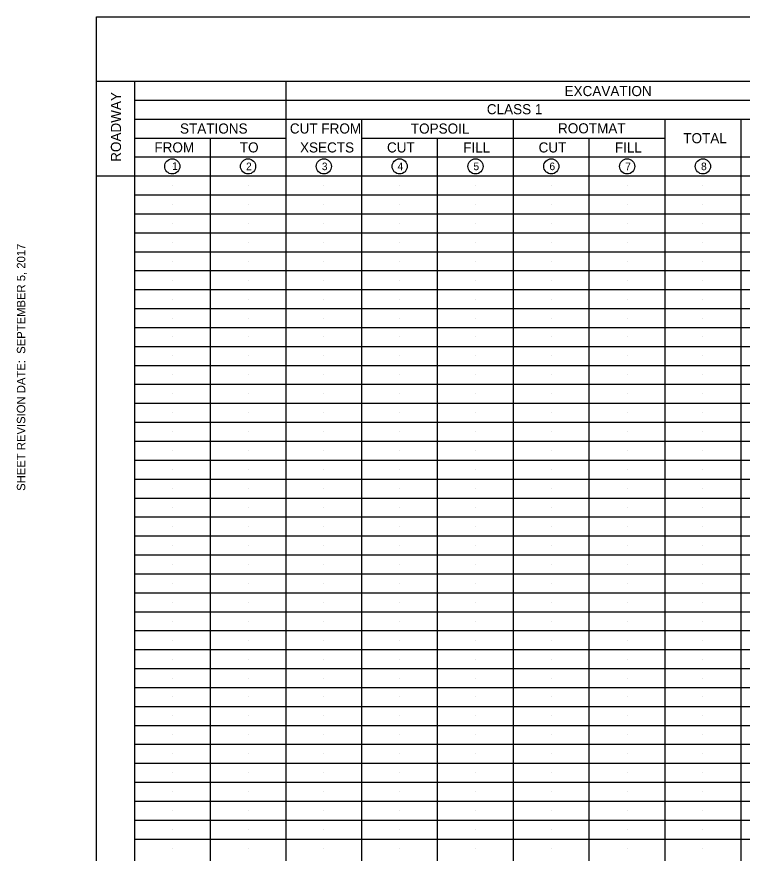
# Model space of a CAD drawing. Extents: x 1.3 to 38.6, y 0 to 21.1.
# Drawn here: x 1.3 to 9.92, y 11.12 to 21.06 of the extents above; entities that cross this region are included whole.
import ezdxf

# ---------------------------------------------------------------- set-up
doc = ezdxf.new("R2010")
doc.units = 0
for name, color, linetype in [('G-ANNO-TABL', 7, 'Continuous'), ('G-ANNO-TITL', 7, 'Continuous'), ('G-USER-LINE', 7, 'Continuous'), ('G-USER-TEXT', 7, 'Continuous')]:
    doc.layers.add(name, color=color, linetype=linetype)

msp = doc.modelspace()

# ---------------------------------------------------------------- linework, layer by layer
at = {"layer": 'G-ANNO-TABL'}
for p, q in [((2.248, 1.1651), (2.248, 21.0551)), ((2.248, 21.055), (22.498, 21.055)), ((2.248, 20.29), (2.249, 20.29)), ((2.248, 20.29), (22.498, 20.29)), ((2.698, 20.29), (2.698, 1.165)), ((4.498, 20.2901), (4.498, 1.1651)), ((2.698, 20.065), (17.098, 20.065)), ((2.698, 19.84), (22.498, 19.84)), ((5.398, 4.54), (5.398, 19.8401)), ((7.198, 4.54), (7.198, 19.8401)), ((8.998, 4.54), (8.998, 19.8401)), ((9.898, 19.8401), (9.898, 4.54)), ((2.698, 19.615), (4.498, 19.615)), ((3.598, 19.6151), (3.598, 17.815)), ((5.398, 19.615), (8.998, 19.615)), ((6.298, 4.54), (6.298, 19.6151)), ((8.098, 4.54), (8.098, 19.6151)), ((2.698, 19.39), (22.498, 19.39)), ((2.248, 19.165), (22.498, 19.165)), ((2.698, 18.94), (22.498, 18.94)), ((2.698, 18.715), (22.498, 18.715)), ((2.698, 18.49), (22.498, 18.49)), ((2.698, 18.265), (22.498, 18.265)), ((2.698, 18.04), (22.498, 18.04)), ((2.698, 17.815), (22.498, 17.815)), ((3.598, 17.815), (3.598, 17.59)), ((2.698, 17.59), (22.498, 17.59)), ((3.598, 17.59), (3.598, 16.915)), ((2.698, 17.365), (22.498, 17.365)), ((2.698, 17.14), (22.498, 17.14)), ((2.698, 16.915), (22.498, 16.915)), ((3.598, 16.915), (3.598, 14.665)), ((2.698, 16.69), (22.498, 16.69)), ((2.698, 16.465), (22.498, 16.465)), ((2.698, 16.24), (22.498, 16.24)), ((2.698, 16.015), (22.498, 16.015)), ((2.698, 15.79), (22.498, 15.79)), ((2.698, 15.565), (22.498, 15.565)), ((2.698, 15.34), (22.498, 15.34)), ((2.698, 15.115), (22.498, 15.115)), ((2.698, 14.89), (22.498, 14.89)), ((2.698, 14.665), (22.498, 14.665)), ((3.598, 14.665), (3.598, 1.165)), ((2.698, 14.44), (22.498, 14.44)), ((2.698, 14.215), (22.498, 14.215)), ((2.698, 13.99), (22.498, 13.99)), ((2.698, 13.765), (22.498, 13.765)), ((2.698, 13.54), (22.498, 13.54)), ((2.698, 13.315), (22.498, 13.315)), ((2.698, 13.09), (22.498, 13.09)), ((2.698, 12.865), (22.498, 12.865)), ((2.698, 12.64), (22.498, 12.64)), ((2.698, 12.415), (22.498, 12.415)), ((2.698, 12.19), (22.498, 12.19)), ((2.698, 11.965), (22.498, 11.965)), ((2.698, 11.74), (22.498, 11.74)), ((2.698, 11.515), (22.498, 11.515)), ((2.698, 11.29), (22.498, 11.29))]:
    msp.add_line(p, q, dxfattribs=at)
at = {"layer": 'G-ANNO-TITL'}
for centre in [(3.1479, 19.278), (4.0479, 19.278), (4.9479, 19.278), (5.8479, 19.278), (6.7479, 19.278), (7.6479, 19.278), (8.5479, 19.278), (9.4479, 19.278)]:
    msp.add_circle(centre, 0.09, dxfattribs=at)
at = {"layer": 'G-USER-LINE'}
for p, q in [((3.148, 19.5025), (3.148, 19.5025)), ((4.048, 19.5025), (4.048, 19.5025)), ((5.848, 19.5025), (5.848, 19.5025)), ((6.748, 19.5025), (6.748, 19.5025)), ((7.648, 19.5025), (7.648, 19.5025)), ((8.548, 19.5025), (8.548, 19.5025)), ((3.148, 19.2775), (3.148, 19.2775)), ((4.048, 19.2775), (4.048, 19.2775)), ((4.948, 19.2775), (4.948, 19.2775)), ((5.848, 19.2775), (5.848, 19.2775)), ((6.748, 19.2775), (6.748, 19.2775)), ((7.648, 19.2775), (7.648, 19.2775)), ((8.548, 19.2775), (8.548, 19.2775)), ((9.448, 19.2775), (9.448, 19.2775)), ((3.148, 19.0525), (3.148, 19.0525)), ((4.048, 19.0525), (4.048, 19.0525)), ((4.948, 19.0525), (4.948, 19.0525)), ((5.848, 19.0525), (5.848, 19.0525)), ((6.748, 19.0525), (6.748, 19.0525)), ((7.648, 19.0525), (7.648, 19.0525)), ((8.548, 19.0525), (8.548, 19.0525)), ((9.448, 19.0525), (9.448, 19.0525)), ((3.148, 18.8275), (3.148, 18.8275)), ((4.048, 18.8275), (4.048, 18.8275)), ((4.948, 18.8275), (4.948, 18.8275)), ((5.848, 18.8275), (5.848, 18.8275)), ((6.748, 18.8275), (6.748, 18.8275)), ((7.648, 18.8275), (7.648, 18.8275)), ((8.548, 18.8275), (8.548, 18.8275)), ((9.448, 18.8275), (9.448, 18.8275)), ((3.148, 18.6025), (3.148, 18.6025)), ((4.048, 18.6025), (4.048, 18.6025)), ((4.948, 18.6025), (4.948, 18.6025)), ((5.848, 18.6025), (5.848, 18.6025)), ((6.748, 18.6025), (6.748, 18.6025)), ((7.648, 18.6025), (7.648, 18.6025)), ((8.548, 18.6025), (8.548, 18.6025)), ((9.448, 18.6025), (9.448, 18.6025)), ((3.148, 18.3775), (3.148, 18.3775)), ((4.048, 18.3775), (4.048, 18.3775)), ((4.948, 18.3775), (4.948, 18.3775)), ((5.848, 18.3775), (5.848, 18.3775)), ((6.748, 18.3775), (6.748, 18.3775)), ((7.648, 18.3775), (7.648, 18.3775)), ((8.548, 18.3775), (8.548, 18.3775)), ((9.448, 18.3775), (9.448, 18.3775)), ((3.148, 18.1525), (3.148, 18.1525)), ((4.048, 18.1525), (4.048, 18.1525)), ((4.948, 18.1525), (4.948, 18.1525)), ((5.848, 18.1525), (5.848, 18.1525)), ((6.748, 18.1525), (6.748, 18.1525)), ((7.648, 18.1525), (7.648, 18.1525)), ((8.548, 18.1525), (8.548, 18.1525)), ((9.448, 18.1525), (9.448, 18.1525)), ((3.148, 17.9275), (3.148, 17.9275)), ((4.048, 17.9275), (4.048, 17.9275)), ((4.948, 17.9275), (4.948, 17.9275)), ((5.848, 17.9275), (5.848, 17.9275)), ((6.748, 17.9275), (6.748, 17.9275)), ((7.648, 17.9275), (7.648, 17.9275)), ((8.548, 17.9275), (8.548, 17.9275)), ((9.448, 17.9275), (9.448, 17.9275)), ((3.148, 17.7025), (3.148, 17.7025)), ((4.048, 17.7025), (4.048, 17.7025)), ((4.948, 17.7025), (4.948, 17.7025)), ((5.848, 17.7025), (5.848, 17.7025)), ((6.748, 17.7025), (6.748, 17.7025)), ((7.648, 17.7025), (7.648, 17.7025)), ((8.548, 17.7025), (8.548, 17.7025)), ((9.448, 17.7025), (9.448, 17.7025)), ((3.148, 17.4775), (3.148, 17.4775)), ((4.048, 17.4775), (4.048, 17.4775)), ((4.948, 17.4775), (4.948, 17.4775)), ((5.848, 17.4775), (5.848, 17.4775)), ((6.748, 17.4775), (6.748, 17.4775)), ((7.648, 17.4775), (7.648, 17.4775)), ((8.548, 17.4775), (8.548, 17.4775)), ((9.448, 17.4775), (9.448, 17.4775)), ((3.148, 17.2525), (3.148, 17.2525)), ((4.048, 17.2525), (4.048, 17.2525)), ((4.948, 17.2525), (4.948, 17.2525)), ((5.848, 17.2525), (5.848, 17.2525)), ((6.748, 17.2525), (6.748, 17.2525)), ((7.648, 17.2525), (7.648, 17.2525)), ((8.548, 17.2525), (8.548, 17.2525)), ((9.448, 17.2525), (9.448, 17.2525)), ((3.148, 17.0275), (3.148, 17.0275)), ((4.048, 17.0275), (4.048, 17.0275)), ((4.948, 17.0275), (4.948, 17.0275)), ((5.848, 17.0275), (5.848, 17.0275)), ((6.748, 17.0275), (6.748, 17.0275)), ((7.648, 17.0275), (7.648, 17.0275)), ((8.548, 17.0275), (8.548, 17.0275)), ((9.448, 17.0275), (9.448, 17.0275)), ((3.148, 16.8025), (3.148, 16.8025)), ((4.048, 16.8025), (4.048, 16.8025)), ((4.948, 16.8025), (4.948, 16.8025)), ((5.848, 16.8025), (5.848, 16.8025)), ((6.748, 16.8025), (6.748, 16.8025)), ((7.648, 16.8025), (7.648, 16.8025)), ((8.548, 16.8025), (8.548, 16.8025)), ((9.448, 16.8025), (9.448, 16.8025)), ((3.148, 16.5775), (3.148, 16.5775)), ((4.048, 16.5775), (4.048, 16.5775)), ((4.948, 16.5775), (4.948, 16.5775)), ((5.848, 16.5775), (5.848, 16.5775)), ((6.748, 16.5775), (6.748, 16.5775)), ((7.648, 16.5775), (7.648, 16.5775)), ((8.548, 16.5775), (8.548, 16.5775)), ((9.448, 16.5775), (9.448, 16.5775)), ((3.148, 16.3525), (3.148, 16.3525)), ((4.048, 16.3525), (4.048, 16.3525)), ((4.948, 16.3525), (4.948, 16.3525)), ((5.848, 16.3525), (5.848, 16.3525)), ((6.748, 16.3525), (6.748, 16.3525)), ((7.648, 16.3525), (7.648, 16.3525)), ((8.548, 16.3525), (8.548, 16.3525)), ((9.448, 16.3525), (9.448, 16.3525)), ((3.148, 16.1275), (3.148, 16.1275)), ((4.048, 16.1275), (4.048, 16.1275)), ((4.948, 16.1275), (4.948, 16.1275)), ((5.848, 16.1275), (5.848, 16.1275)), ((6.748, 16.1275), (6.748, 16.1275)), ((7.648, 16.1275), (7.648, 16.1275)), ((8.548, 16.1275), (8.548, 16.1275)), ((9.448, 16.1275), (9.448, 16.1275)), ((3.148, 15.9025), (3.148, 15.9025)), ((4.048, 15.9025), (4.048, 15.9025)), ((4.948, 15.9025), (4.948, 15.9025)), ((5.848, 15.9025), (5.848, 15.9025)), ((6.748, 15.9025), (6.748, 15.9025)), ((7.648, 15.9025), (7.648, 15.9025)), ((8.548, 15.9025), (8.548, 15.9025)), ((9.448, 15.9025), (9.448, 15.9025)), ((3.148, 15.6775), (3.148, 15.6775)), ((4.048, 15.6775), (4.048, 15.6775)), ((4.948, 15.6775), (4.948, 15.6775)), ((5.848, 15.6775), (5.848, 15.6775)), ((6.748, 15.6775), (6.748, 15.6775)), ((7.648, 15.6775), (7.648, 15.6775)), ((8.548, 15.6775), (8.548, 15.6775)), ((9.448, 15.6775), (9.448, 15.6775)), ((3.148, 15.4525), (3.148, 15.4525)), ((4.048, 15.4525), (4.048, 15.4525)), ((4.948, 15.4525), (4.948, 15.4525)), ((5.848, 15.4525), (5.848, 15.4525)), ((6.748, 15.4525), (6.748, 15.4525)), ((7.648, 15.4525), (7.648, 15.4525)), ((8.548, 15.4525), (8.548, 15.4525)), ((9.448, 15.4525), (9.448, 15.4525)), ((3.148, 15.2275), (3.148, 15.2275)), ((4.048, 15.2275), (4.048, 15.2275)), ((4.948, 15.2275), (4.948, 15.2275)), ((5.848, 15.2275), (5.848, 15.2275)), ((6.748, 15.2275), (6.748, 15.2275)), ((7.648, 15.2275), (7.648, 15.2275)), ((8.548, 15.2275), (8.548, 15.2275)), ((9.448, 15.2275), (9.448, 15.2275)), ((3.148, 15.0025), (3.148, 15.0025)), ((4.048, 15.0025), (4.048, 15.0025)), ((4.948, 15.0025), (4.948, 15.0025)), ((5.848, 15.0025), (5.848, 15.0025)), ((6.748, 15.0025), (6.748, 15.0025)), ((7.648, 15.0025), (7.648, 15.0025)), ((8.548, 15.0025), (8.548, 15.0025)), ((9.448, 15.0025), (9.448, 15.0025)), ((3.148, 14.7775), (3.148, 14.7775)), ((4.048, 14.7775), (4.048, 14.7775)), ((4.948, 14.7775), (4.948, 14.7775)), ((5.848, 14.7775), (5.848, 14.7775)), ((6.748, 14.7775), (6.748, 14.7775)), ((7.648, 14.7775), (7.648, 14.7775)), ((8.548, 14.7775), (8.548, 14.7775)), ((9.448, 14.7775), (9.448, 14.7775)), ((3.148, 14.5525), (3.148, 14.5525)), ((4.048, 14.5525), (4.048, 14.5525)), ((4.948, 14.5525), (4.948, 14.5525)), ((5.848, 14.5525), (5.848, 14.5525)), ((6.748, 14.5525), (6.748, 14.5525)), ((7.648, 14.5525), (7.648, 14.5525)), ((8.548, 14.5525), (8.548, 14.5525)), ((9.448, 14.5525), (9.448, 14.5525)), ((3.148, 14.3275), (3.148, 14.3275)), ((4.048, 14.3275), (4.048, 14.3275)), ((4.948, 14.3275), (4.948, 14.3275)), ((5.848, 14.3275), (5.848, 14.3275)), ((6.748, 14.3275), (6.748, 14.3275)), ((7.648, 14.3275), (7.648, 14.3275)), ((8.548, 14.3275), (8.548, 14.3275)), ((9.448, 14.3275), (9.448, 14.3275)), ((3.148, 14.1025), (3.148, 14.1025)), ((4.048, 14.1025), (4.048, 14.1025)), ((4.948, 14.1025), (4.948, 14.1025)), ((5.848, 14.1025), (5.848, 14.1025)), ((6.748, 14.1025), (6.748, 14.1025)), ((7.648, 14.1025), (7.648, 14.1025)), ((8.548, 14.1025), (8.548, 14.1025)), ((9.448, 14.1025), (9.448, 14.1025)), ((3.148, 13.8775), (3.148, 13.8775)), ((4.048, 13.8775), (4.048, 13.8775)), ((4.948, 13.8775), (4.948, 13.8775)), ((5.848, 13.8775), (5.848, 13.8775)), ((6.748, 13.8775), (6.748, 13.8775)), ((7.648, 13.8775), (7.648, 13.8775)), ((8.548, 13.8775), (8.548, 13.8775)), ((9.448, 13.8775), (9.448, 13.8775)), ((3.148, 13.6525), (3.148, 13.6525)), ((4.048, 13.6525), (4.048, 13.6525)), ((4.948, 13.6525), (4.948, 13.6525)), ((5.848, 13.6525), (5.848, 13.6525)), ((6.748, 13.6525), (6.748, 13.6525)), ((7.648, 13.6525), (7.648, 13.6525)), ((8.548, 13.6525), (8.548, 13.6525)), ((9.448, 13.6525), (9.448, 13.6525)), ((3.148, 13.4275), (3.148, 13.4275)), ((4.048, 13.4275), (4.048, 13.4275)), ((4.948, 13.4275), (4.948, 13.4275)), ((5.848, 13.4275), (5.848, 13.4275)), ((6.748, 13.4275), (6.748, 13.4275)), ((7.648, 13.4275), (7.648, 13.4275)), ((8.548, 13.4275), (8.548, 13.4275)), ((9.448, 13.4275), (9.448, 13.4275)), ((3.148, 13.2025), (3.148, 13.2025)), ((4.048, 13.2025), (4.048, 13.2025)), ((4.948, 13.2025), (4.948, 13.2025)), ((5.848, 13.2025), (5.848, 13.2025)), ((6.748, 13.2025), (6.748, 13.2025)), ((7.648, 13.2025), (7.648, 13.2025)), ((8.548, 13.2025), (8.548, 13.2025)), ((9.448, 13.2025), (9.448, 13.2025)), ((3.148, 12.9775), (3.148, 12.9775)), ((4.048, 12.9775), (4.048, 12.9775)), ((4.948, 12.9775), (4.948, 12.9775)), ((5.848, 12.9775), (5.848, 12.9775)), ((6.748, 12.9775), (6.748, 12.9775)), ((7.648, 12.9775), (7.648, 12.9775)), ((8.548, 12.9775), (8.548, 12.9775)), ((9.448, 12.9775), (9.448, 12.9775)), ((3.148, 12.7525), (3.148, 12.7525)), ((4.048, 12.7525), (4.048, 12.7525)), ((4.948, 12.7525), (4.948, 12.7525)), ((5.848, 12.7525), (5.848, 12.7525)), ((6.748, 12.7525), (6.748, 12.7525)), ((7.648, 12.7525), (7.648, 12.7525)), ((8.548, 12.7525), (8.548, 12.7525)), ((9.448, 12.7525), (9.448, 12.7525)), ((3.148, 12.5275), (3.148, 12.5275)), ((4.048, 12.5275), (4.048, 12.5275)), ((4.948, 12.5275), (4.948, 12.5275)), ((5.848, 12.5275), (5.848, 12.5275)), ((6.748, 12.5275), (6.748, 12.5275)), ((7.648, 12.5275), (7.648, 12.5275)), ((8.548, 12.5275), (8.548, 12.5275)), ((9.448, 12.5275), (9.448, 12.5275)), ((3.148, 12.3025), (3.148, 12.3025)), ((4.048, 12.3025), (4.048, 12.3025)), ((4.948, 12.3025), (4.948, 12.3025)), ((5.848, 12.3025), (5.848, 12.3025)), ((6.748, 12.3025), (6.748, 12.3025)), ((7.648, 12.3025), (7.648, 12.3025)), ((8.548, 12.3025), (8.548, 12.3025)), ((9.448, 12.3025), (9.448, 12.3025)), ((3.148, 12.0775), (3.148, 12.0775)), ((4.048, 12.0775), (4.048, 12.0775)), ((4.948, 12.0775), (4.948, 12.0775)), ((5.848, 12.0775), (5.848, 12.0775)), ((6.748, 12.0775), (6.748, 12.0775)), ((7.648, 12.0775), (7.648, 12.0775)), ((8.548, 12.0775), (8.548, 12.0775)), ((9.448, 12.0775), (9.448, 12.0775)), ((3.148, 11.8525), (3.148, 11.8525)), ((4.048, 11.8525), (4.048, 11.8525)), ((4.948, 11.8525), (4.948, 11.8525)), ((5.848, 11.8525), (5.848, 11.8525)), ((6.748, 11.8525), (6.748, 11.8525)), ((7.648, 11.8525), (7.648, 11.8525)), ((8.548, 11.8525), (8.548, 11.8525)), ((9.448, 11.8525), (9.448, 11.8525)), ((3.148, 11.6275), (3.148, 11.6275)), ((4.048, 11.6275), (4.048, 11.6275)), ((4.948, 11.6275), (4.948, 11.6275)), ((5.848, 11.6275), (5.848, 11.6275)), ((6.748, 11.6275), (6.748, 11.6275)), ((7.648, 11.6275), (7.648, 11.6275)), ((8.548, 11.6275), (8.548, 11.6275)), ((9.448, 11.6275), (9.448, 11.6275)), ((3.148, 11.4025), (3.148, 11.4025)), ((4.048, 11.4025), (4.048, 11.4025)), ((4.948, 11.4025), (4.948, 11.4025)), ((5.848, 11.4025), (5.848, 11.4025)), ((6.748, 11.4025), (6.748, 11.4025)), ((7.648, 11.4025), (7.648, 11.4025)), ((8.548, 11.4025), (8.548, 11.4025)), ((9.448, 11.4025), (9.448, 11.4025)), ((3.148, 11.1775), (3.148, 11.1775)), ((4.048, 11.1775), (4.048, 11.1775)), ((4.948, 11.1775), (4.948, 11.1775)), ((5.848, 11.1775), (5.848, 11.1775)), ((6.748, 11.1775), (6.748, 11.1775)), ((7.648, 11.1775), (7.648, 11.1775)), ((8.548, 11.1775), (8.548, 11.1775)), ((9.448, 11.1775), (9.448, 11.1775))]:
    msp.add_line(p, q, dxfattribs=at)

# ---------------------------------------------------------------- texts
at = {"layer": 'G-ANNO-TITL'}
for s, height, p in [('EXCAVATION', 0.12, (7.8055, 20.1125)), ('CLASS 1', 0.12, (6.8825, 19.897)), ('STATIONS', 0.12, (3.2397, 19.6675)), ('CUT FROM', 0.12, (4.544, 19.668)), ('TOPSOIL', 0.12, (5.9803, 19.667)), ('ROOTMAT', 0.12, (7.7277, 19.67)), ('TOTAL', 0.12, (9.2149, 19.553)), ('FROM', 0.12, (2.936, 19.4435)), ('TO', 0.12, (3.9501, 19.4435)), ('XSECTS', 0.12, (4.6647, 19.443)), ('CUT', 0.12, (5.6973, 19.443)), ('FILL', 0.12, (6.6019, 19.4425)), ('CUT', 0.12, (7.4973, 19.443)), ('FILL', 0.12, (8.4019, 19.4425)), ('1', 0.09, (3.146, 19.236)), ('2', 0.09, (4.024, 19.233)), ('3', 0.09, (4.924, 19.233)), ('4', 0.09, (5.822, 19.233)), ('5', 0.09, (6.724, 19.233)), ('6', 0.09, (7.626, 19.233)), ('7', 0.09, (8.526, 19.233)), ('8', 0.09, (9.426, 19.233))]:
    msp.add_text(s, height=height, dxfattribs=at).set_placement(p)
msp.add_text('ROADWAY', height=0.12, rotation=90, dxfattribs=at).set_placement((2.5395, 19.3317))
at = {"layer": 'G-USER-TEXT'}
msp.add_text('SHEET REVISION DATE:  SEPTEMBER 5, 2017', height=0.1, rotation=90, dxfattribs=at).set_placement((1.403, 15.425))

doc.saveas('drawing.dxf')
